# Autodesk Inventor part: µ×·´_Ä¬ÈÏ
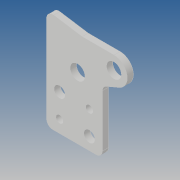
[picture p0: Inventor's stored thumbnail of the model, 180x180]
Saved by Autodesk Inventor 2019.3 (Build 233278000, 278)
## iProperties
Created: 2012-10
Part Number: µ×·´_Ä¬ÈÏ
Material: Ogólny
Document SubType Name: Modeling
Designer: CADENGINEERING4
Density: 1 g/cm^3
Appearance: Domyślna
Author: CADENGINEERING4
Revision Number: ÈÎºÎ
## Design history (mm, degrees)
feature "NONE"
node "Bryła1"
